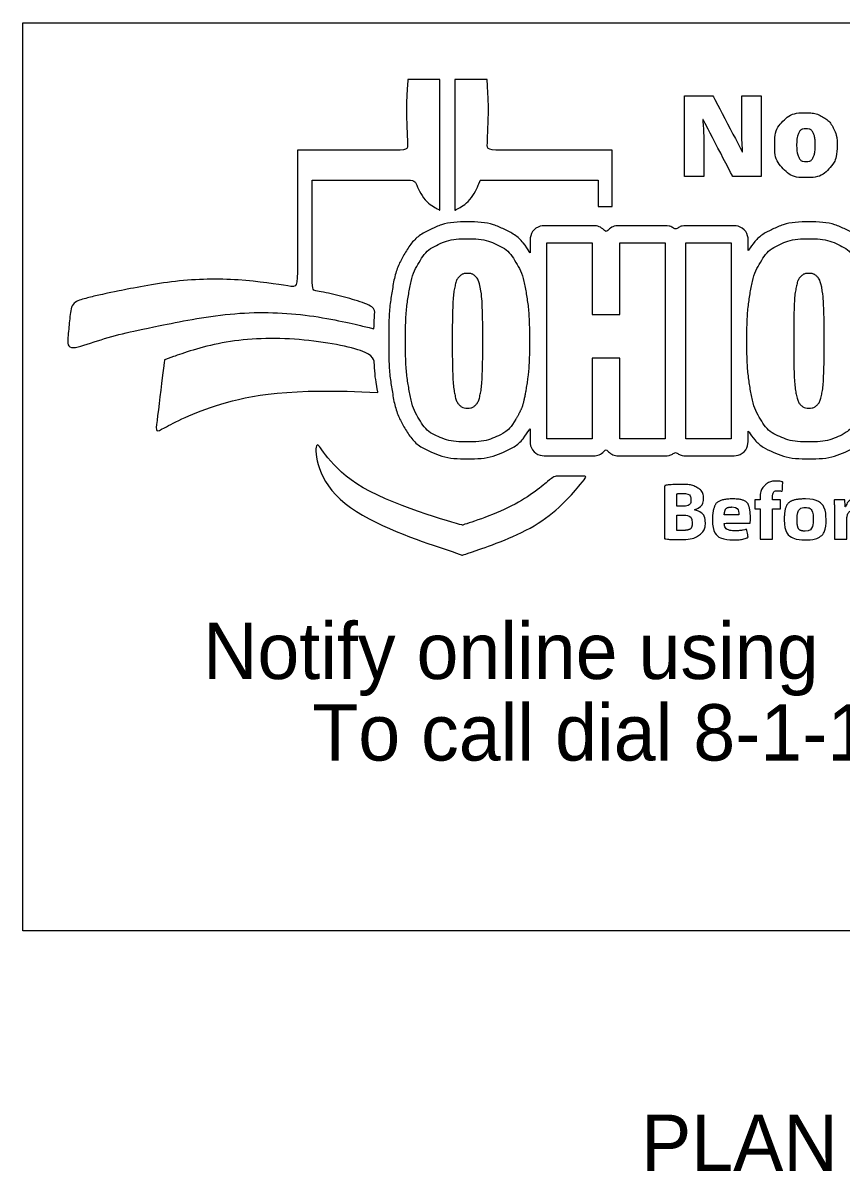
# Model space of a CAD drawing. Extents: x 0 to 70.2, y 0 to 31.4.
# Drawn here: x 40.226 to 42.259, y 11.816 to 14.667 of the extents above; entities that cross this region are included whole.
import ezdxf

# ---------------------------------------------------------------- set-up
doc = ezdxf.new("R2010")
doc.units = 0
for name, color, linetype in [('Default', 7, 'Continuous'), ('SH_Data', 7, 'Continuous'), ('SH_Text', 7, 'Continuous')]:
    doc.layers.add(name, color=color, linetype=linetype)

msp = doc.modelspace()

# ---------------------------------------------------------------- linework, layer by layer
at = {"layer": 'Default'}
for points, degree in [([(41.0979, 13.9079), (41.0979, 13.9079), (41.0978, 13.9079), (41.0978, 13.9079), (40.93, 13.9477), (40.7416, 13.9515), (40.5464, 13.9116), (40.4729, 13.8965), (40.402, 13.8758), (40.3341, 13.8504), (40.3379, 13.8906), (40.3419, 13.9332), (40.3457, 13.9734), (40.3777, 13.9822), (40.4099, 13.9906), (40.443, 13.9973), (40.6054, 14.0305), (40.7629, 14.0333), (40.9078, 14.0103), (40.9078, 14.0103), (40.9078, 14.3512), (40.9078, 14.3512), (40.9078, 14.3512), (41.1822, 14.3512), (41.1822, 14.3512), (41.1773, 14.46), (41.1822, 14.5269), (41.1822, 14.5269), (41.1822, 14.5269), (41.262, 14.5269), (41.262, 14.5269), (41.262, 14.5269), (41.262, 14.2022), (41.262, 14.2022), (41.262, 14.2022), (41.2221, 14.2228), (41.1987, 14.2769), (41.1987, 14.2769), (40.9446, 14.2769), (40.9446, 14.2769), (40.9446, 14.2769), (40.9446, 14.0038), (40.9446, 14.0038), (40.9988, 13.9935), (41.0512, 13.9795), (41.1012, 13.962), (41.0996, 13.9453), (41.0985, 13.9274), (41.0979, 13.9079)], 3), ([(41.3624, 14.277), (41.3624, 14.277), (41.3625, 14.277), (41.3625, 14.277), (41.339, 14.223), (41.2991, 14.2023), (41.2991, 14.2023), (41.2991, 14.2023), (41.2991, 14.5269), (41.2991, 14.5269), (41.2991, 14.5269), (41.3789, 14.5269), (41.3789, 14.5269), (41.3789, 14.5269), (41.3839, 14.46), (41.3789, 14.3512), (41.3789, 14.3512), (41.6898, 14.3512), (41.6898, 14.3512), (41.6898, 14.3512), (41.6898, 14.2115), (41.6898, 14.2115), (41.6898, 14.2115), (41.655, 14.2115), (41.655, 14.2115), (41.655, 14.2115), (41.655, 14.277), (41.655, 14.277), (41.655, 14.277), (41.3624, 14.277), (41.3624, 14.277)], 3), ([(42.0604, 14.286), (42.0604, 14.286), (42.0604, 14.4866), (42.0604, 14.4866), (42.0604, 14.4866), (42.0121, 14.4866), (42.0121, 14.4866), (42.0121, 14.4866), (42.0121, 14.3959), (42.0121, 14.3959), (42.0121, 14.3836), (42.0127, 14.3674), (42.014, 14.3472), (42.014, 14.3472), (42.0132, 14.3472), (42.0132, 14.3472), (42.0132, 14.3472), (41.9402, 14.4866), (41.9402, 14.4866), (41.9402, 14.4866), (41.8694, 14.4866), (41.8694, 14.4866), (41.8694, 14.4866), (41.8694, 14.286), (41.8694, 14.286), (41.8694, 14.286), (41.9174, 14.286), (41.9174, 14.286), (41.9174, 14.286), (41.9174, 14.3764), (41.9174, 14.3764), (41.9174, 14.3881), (41.9166, 14.4051), (41.9149, 14.4273), (41.9149, 14.4273), (41.9161, 14.4273), (41.9161, 14.4273), (41.9161, 14.4273), (41.9893, 14.286), (41.9893, 14.286), (41.9893, 14.286), (42.0604, 14.286), (42.0604, 14.286)], 3), ([(42.249, 14.3641), (42.249, 14.3803), (42.2458, 14.3944), (42.2394, 14.4065), (42.2331, 14.4186), (42.224, 14.4279), (42.2123, 14.4344), (42.2006, 14.4409), (42.1872, 14.4442), (42.1719, 14.4442), (42.1472, 14.4442), (42.128, 14.4371), (42.1143, 14.4231), (42.1007, 14.4091), (42.0938, 14.3894), (42.0938, 14.3641), (42.0938, 14.3393), (42.1008, 14.3196), (42.1148, 14.3051), (42.1287, 14.2905), (42.1475, 14.2833), (42.171, 14.2833), (42.1956, 14.2833), (42.2148, 14.2904), (42.2284, 14.3046), (42.2421, 14.3188), (42.249, 14.3387), (42.249, 14.3641)], 3), ([(42.1483, 14.3641), (42.1483, 14.3774), (42.15, 14.3874), (42.1536, 14.3941), (42.1572, 14.4009), (42.1631, 14.4042), (42.1714, 14.4042), (42.1797, 14.4042), (42.1857, 14.4009), (42.1891, 14.3941), (42.1926, 14.3873), (42.1944, 14.3773), (42.1944, 14.3641), (42.1944, 14.3507), (42.1927, 14.3406), (42.1893, 14.3336), (42.1858, 14.3266), (42.1799, 14.3231), (42.1716, 14.3231), (42.1632, 14.3231), (42.1572, 14.3266), (42.1536, 14.3336), (42.15, 14.3406), (42.1483, 14.3507), (42.1483, 14.3641)], 3), ([(42.6795, 14.1274), (42.6478, 14.1579), (42.6036, 14.1726), (42.5445, 14.1726), (42.4336, 14.1726), (42.3701, 14.1168), (42.364, 14.0153), (42.3577, 14.0465), (42.3483, 14.0725), (42.3353, 14.0942), (42.319, 14.1217), (42.2968, 14.1421), (42.2695, 14.155), (42.2442, 14.167), (42.2138, 14.1731), (42.179, 14.1731), (42.1442, 14.1731), (42.1139, 14.167), (42.0886, 14.155), (42.0638, 14.1433), (42.0436, 14.1251), (42.0278, 14.1014), (42.0278, 14.1014), (42.0278, 14.1215), (42.0278, 14.1215), (42.0278, 14.1447), (42.0089, 14.1635), (41.9857, 14.1635), (41.9857, 14.1635), (41.8735, 14.1635), (41.8735, 14.1635), (41.8635, 14.1635), (41.8547, 14.1595), (41.8475, 14.1538), (41.8402, 14.1595), (41.8314, 14.1635), (41.8215, 14.1635), (41.8215, 14.1635), (41.7092, 14.1635), (41.7092, 14.1635), (41.6949, 14.1635), (41.6824, 14.1565), (41.6748, 14.1456), (41.6672, 14.1565), (41.6546, 14.1635), (41.6404, 14.1635), (41.6404, 14.1635), (41.5281, 14.1635), (41.5281, 14.1635), (41.5049, 14.1635), (41.4861, 14.1448), (41.4861, 14.1215), (41.4861, 14.1215), (41.4861, 14.0953), (41.4861, 14.0953), (41.4698, 14.1222), (41.448, 14.1423), (41.421, 14.155), (41.3958, 14.167), (41.3653, 14.1731), (41.3305, 14.1731), (41.2957, 14.1731), (41.2653, 14.167), (41.2401, 14.155), (41.2127, 14.1421), (41.1907, 14.1217), (41.1742, 14.0942), (41.1595, 14.0695), (41.1489, 14.0381), (41.1429, 14.001), (41.1373, 13.9668), (41.1345, 13.9254), (41.1345, 13.878), (41.1345, 13.8306), (41.1373, 13.7891), (41.1429, 13.7549), (41.1489, 13.7178), (41.1595, 13.6864), (41.1742, 13.6617), (41.1908, 13.6339), (41.2134, 13.6135), (41.2411, 13.6014), (41.266, 13.5905), (41.2961, 13.5849), (41.3304, 13.5849), (41.3647, 13.5849), (41.3948, 13.5905), (41.4197, 13.6014), (41.4472, 13.6134), (41.4694, 13.6334), (41.486, 13.6606), (41.486, 13.6606), (41.486, 13.6344), (41.486, 13.6344), (41.486, 13.6113), (41.5048, 13.5924), (41.528, 13.5924), (41.528, 13.5924), (41.6403, 13.5924), (41.6403, 13.5924), (41.6546, 13.5924), (41.6671, 13.5995), (41.6747, 13.6103), (41.6823, 13.5995), (41.6948, 13.5924), (41.7091, 13.5924), (41.7091, 13.5924), (41.8214, 13.5924), (41.8214, 13.5924), (41.8313, 13.5924), (41.8401, 13.5964), (41.8474, 13.6022), (41.8546, 13.5964), (41.8634, 13.5924), (41.8734, 13.5924), (41.8734, 13.5924), (41.9856, 13.5924), (41.9856, 13.5924), (42.0088, 13.5924), (42.0277, 13.6112), (42.0277, 13.6344), (42.0277, 13.6344), (42.0277, 13.6546), (42.0277, 13.6546), (42.0437, 13.6305), (42.0644, 13.6125), (42.0896, 13.6014), (42.1145, 13.5905), (42.1446, 13.5849), (42.1789, 13.5849), (42.2132, 13.5849), (42.2433, 13.5905), (42.2683, 13.6014), (42.296, 13.6135), (42.3186, 13.6339), (42.3351, 13.6616), (42.3459, 13.6796), (42.3542, 13.7005), (42.3603, 13.7248), (42.3655, 13.6846), (42.3805, 13.652), (42.4056, 13.628), (42.4378, 13.5969), (42.4832, 13.5819), (42.5443, 13.5819), (42.6302, 13.5819), (42.6878, 13.6148), (42.7136, 13.6753), (42.7136, 13.6753), (42.7221, 13.6753), (42.7221, 13.6753), (42.7221, 13.6753), (42.7221, 13.6279), (42.7221, 13.6279), (42.7221, 13.6055), (42.7403, 13.5873), (42.7626, 13.5873), (42.7626, 13.5873), (42.8865, 13.5873), (42.8865, 13.5873), (42.9088, 13.5873), (42.927, 13.6055), (42.927, 13.6279), (42.927, 13.6279), (42.927, 13.9), (42.927, 13.9), (42.9284, 13.9), (42.9297, 13.8998), (42.931, 13.8998), (42.931, 13.8998), (42.931, 13.6279), (42.931, 13.6279), (42.931, 13.6055), (42.9492, 13.5873), (42.9716, 13.5873), (42.9716, 13.5873), (43.0954, 13.5873), (43.0954, 13.5873), (43.1103, 13.5873), (43.1232, 13.5955), (43.1302, 13.6074), (43.136, 13.5995), (43.1452, 13.5943), (43.1558, 13.5943), (43.1558, 13.5943), (43.2262, 13.5943), (43.2262, 13.5943), (43.2437, 13.5943), (43.258, 13.6085), (43.258, 13.6261), (43.258, 13.6261), (43.258, 13.6546), (43.258, 13.6546), (43.2594, 13.6513), (43.2604, 13.6477), (43.262, 13.6446), (43.2715, 13.6267), (43.2857, 13.6128), (43.3042, 13.6029), (43.3219, 13.5936), (43.3439, 13.589), (43.3715, 13.589), (43.399, 13.589), (43.4208, 13.5942), (43.4384, 13.6044), (43.4557, 13.6145), (43.4691, 13.6284), (43.4786, 13.6455), (43.4786, 13.6455), (43.4786, 13.6261), (43.4786, 13.6261), (43.4786, 13.6085), (43.4928, 13.5943), (43.5104, 13.5943), (43.5104, 13.5943), (43.5859, 13.5943), (43.5859, 13.5943), (43.6035, 13.5943), (43.6177, 13.6085), (43.6177, 13.6261), (43.6177, 13.6261), (43.6177, 13.7658), (43.6177, 13.7658), (43.6177, 13.7738), (43.6188, 13.7774), (43.6186, 13.7778), (43.6202, 13.7787), (43.6267, 13.7798), (43.6341, 13.7791), (43.6363, 13.7789), (43.6385, 13.7785), (43.641, 13.7781), (43.6426, 13.7778), (43.644, 13.7783), (43.6456, 13.7782), (43.6454, 13.772), (43.6449, 13.7665), (43.6449, 13.7597), (43.6449, 13.7303), (43.6472, 13.7067), (43.6519, 13.6875), (43.6566, 13.6683), (43.6628, 13.653), (43.6707, 13.6409), (43.6677, 13.6393), (43.6649, 13.6373), (43.6625, 13.6348), (43.6565, 13.6288), (43.6532, 13.6205), (43.6534, 13.612), (43.6537, 13.5928), (43.6573, 13.5762), (43.6641, 13.5627), (43.6711, 13.5484), (43.6811, 13.5369), (43.6937, 13.5283), (43.7052, 13.5206), (43.7185, 13.5152), (43.7332, 13.5124), (43.7458, 13.5099), (43.7592, 13.5087), (43.7733, 13.5087), (43.7893, 13.5087), (43.8046, 13.5105), (43.8188, 13.5142), (43.8347, 13.5184), (43.8488, 13.5255), (43.8607, 13.5353), (43.8733, 13.5454), (43.8832, 13.559), (43.8901, 13.5755), (43.8966, 13.5911), (43.9, 13.6095), (43.9, 13.6304), (43.9, 13.6304), (43.9, 13.8824), (43.9, 13.8824), (43.9, 13.9), (43.8857, 13.9142), (43.8681, 13.9142), (43.8681, 13.9142), (43.8681, 13.9141), (43.8681, 13.9141)], 3), ([(41.4505, 13.6832), (41.4384, 13.663), (41.4226, 13.6485), (41.4028, 13.6399), (41.3831, 13.6313), (41.3589, 13.6269), (41.3303, 13.6269), (41.3017, 13.6269), (41.2775, 13.6312), (41.2579, 13.6399), (41.2381, 13.6485), (41.2223, 13.663), (41.2102, 13.6832), (41.1981, 13.7034), (41.1895, 13.7296), (41.1842, 13.7617), (41.1789, 13.7937), (41.1764, 13.8325), (41.1764, 13.878), (41.1764, 13.9234), (41.179, 13.9622), (41.1842, 13.9943), (41.1895, 14.0263), (41.1981, 14.0525), (41.2102, 14.0727), (41.2223, 14.093), (41.2381, 14.1077), (41.2579, 14.1171), (41.2776, 14.1265), (41.3018, 14.1311), (41.3303, 14.1311), (41.3588, 14.1311), (41.3831, 14.1264), (41.4028, 14.1171), (41.4226, 14.1078), (41.4384, 14.093), (41.4505, 14.0727), (41.4626, 14.0525), (41.4712, 14.0263), (41.4765, 13.9943), (41.4817, 13.9622), (41.4843, 13.9234), (41.4843, 13.878), (41.4843, 13.8325), (41.4817, 13.7937), (41.4765, 13.7617)], 3), ([(41.709, 13.6344), (41.709, 13.6344), (41.709, 13.8351), (41.709, 13.8351), (41.709, 13.8351), (41.6402, 13.8351), (41.6402, 13.8351), (41.6402, 13.8351), (41.6402, 13.6344), (41.6402, 13.6344), (41.6402, 13.6344), (41.5279, 13.6344), (41.5279, 13.6344), (41.5279, 13.6344), (41.5279, 14.1216), (41.5279, 14.1216), (41.5279, 14.1216), (41.6402, 14.1216), (41.6402, 14.1216), (41.6402, 14.1216), (41.6402, 13.9429), (41.6402, 13.9429), (41.6402, 13.9429), (41.709, 13.9429), (41.709, 13.9429), (41.709, 13.9429), (41.709, 14.1216), (41.709, 14.1216), (41.709, 14.1216), (41.8213, 14.1216), (41.8213, 14.1216), (41.8213, 14.1216), (41.8213, 13.6344), (41.8213, 13.6344)], 3), ([(41.8732, 13.6344), (41.8732, 13.6344), (41.8732, 14.1216), (41.8732, 14.1216), (41.8732, 14.1216), (41.9854, 14.1216), (41.9854, 14.1216), (41.9854, 14.1216), (41.9854, 13.6344), (41.9854, 13.6344)], 3), ([(42.2988, 13.6832), (42.2867, 13.663), (42.2709, 13.6485), (42.2512, 13.6399), (42.2314, 13.6313), (42.2073, 13.6269), (42.1786, 13.6269), (42.15, 13.6269), (42.1259, 13.6312), (42.1062, 13.6399), (42.0865, 13.6485), (42.0707, 13.663), (42.0585, 13.6832), (42.0464, 13.7034), (42.0378, 13.7296), (42.0325, 13.7617), (42.0273, 13.7937), (42.0247, 13.8325), (42.0247, 13.878), (42.0247, 13.9234), (42.0274, 13.9622), (42.0325, 13.9943), (42.0378, 14.0263), (42.0464, 14.0525), (42.0585, 14.0727), (42.0707, 14.093), (42.0865, 14.1077), (42.1062, 14.1171), (42.126, 14.1265), (42.1501, 14.1311), (42.1786, 14.1311), (42.2072, 14.1311), (42.2314, 14.1264), (42.2512, 14.1171), (42.2709, 14.1078), (42.2867, 14.093), (42.2988, 14.0727), (42.311, 14.0525), (42.3196, 14.0263), (42.3248, 13.9943), (42.33, 13.9622), (42.3327, 13.9234), (42.3327, 13.878), (42.3327, 13.8325), (42.33, 13.7937), (42.3248, 13.7617)], 3), ([(41.3621, 14.011), (41.3646, 13.9983), (41.3664, 13.9811), (41.3671, 13.9595), (41.3679, 13.9379), (41.3683, 13.9107), (41.3683, 13.878), (41.3683, 13.8452), (41.3679, 13.8181), (41.3671, 13.7965), (41.3664, 13.7749), (41.3647, 13.7577), (41.3621, 13.745), (41.3594, 13.7323), (41.3556, 13.7234), (41.3506, 13.7184), (41.3456, 13.7134), (41.3389, 13.7109), (41.3304, 13.7109), (41.3219, 13.7109), (41.3153, 13.7134), (41.3102, 13.7184), (41.3052, 13.7234), (41.3014, 13.7323), (41.2987, 13.745), (41.2962, 13.7577), (41.2944, 13.7749), (41.2937, 13.7965), (41.2929, 13.8181), (41.2925, 13.8452), (41.2925, 13.878), (41.2925, 13.9107), (41.2929, 13.9379), (41.2937, 13.9595), (41.2944, 13.9811), (41.2961, 13.9983), (41.2987, 14.011), (41.3013, 14.0237), (41.3051, 14.0326), (41.3102, 14.0376), (41.3153, 14.0425), (41.3219, 14.0451), (41.3304, 14.0451), (41.3389, 14.0451), (41.3455, 14.0425), (41.3506, 14.0376), (41.3556, 14.0326), (41.3594, 14.0237), (41.3621, 14.011)], 3), ([(42.2105, 14.011), (42.213, 13.9983), (42.2148, 13.9811), (42.2156, 13.9595), (42.2164, 13.9379), (42.2168, 13.9107), (42.2168, 13.878), (42.2168, 13.8452), (42.2164, 13.8181), (42.2156, 13.7965), (42.2148, 13.7749), (42.2131, 13.7577), (42.2105, 13.745), (42.2079, 13.7323), (42.2041, 13.7234), (42.1991, 13.7184), (42.1941, 13.7134), (42.1873, 13.7109), (42.1788, 13.7109), (42.1703, 13.7109), (42.1637, 13.7134), (42.1586, 13.7184), (42.1536, 13.7234), (42.1498, 13.7323), (42.1472, 13.745), (42.1446, 13.7577), (42.1429, 13.7749), (42.1421, 13.7965), (42.1413, 13.8181), (42.1409, 13.8452), (42.1409, 13.878), (42.1409, 13.9107), (42.1413, 13.9379), (42.1421, 13.9595), (42.1429, 13.9811), (42.1445, 13.9983), (42.1472, 14.011), (42.1497, 14.0237), (42.1535, 14.0326), (42.1586, 14.0376), (42.1637, 14.0425), (42.1703, 14.0451), (42.1788, 14.0451), (42.1873, 14.0451), (42.194, 14.0425), (42.1991, 14.0376), (42.2041, 14.0326), (42.2079, 14.0237), (42.2105, 14.011)], 3), ([(41.1078, 13.7492), (40.8886, 13.7617), (40.6907, 13.723), (40.5552, 13.6498), (40.5552, 13.6498), (40.5771, 13.8283), (40.5771, 13.8283), (40.5771, 13.8283), (40.5771, 13.8304), (40.5771, 13.8304), (40.7124, 13.879), (40.8978, 13.8895), (41.0978, 13.8533), (41.0987, 13.8184), (41.101, 13.7877), (41.1053, 13.7616), (41.106, 13.7573), (41.1069, 13.7533), (41.1078, 13.7492)], 3), ([(41.4765, 13.7617), (41.4712, 13.7296), (41.4626, 13.7034), (41.4505, 13.6832)], 2), ([(41.8213, 13.6344), (41.8213, 13.6344), (41.709, 13.6344), (41.709, 13.6344)], 2), ([(41.9854, 13.6344), (41.9854, 13.6344), (41.8732, 13.6344), (41.8732, 13.6344)], 2), ([(41.3178, 13.4201), (41.3178, 13.4201), (41.447, 13.4598), (41.5455, 13.5417), (41.5455, 13.5417), (41.6282, 13.5417), (41.6282, 13.5417), (41.5223, 13.4152), (41.3176, 13.3455), (41.3176, 13.3455), (41.3176, 13.3455), (40.9555, 13.4687), (40.9454, 13.6854), (41.0017, 13.5031), (41.3178, 13.4201), (41.3178, 13.4201)], 3), ([(41.8942, 13.4583), (41.9096, 13.4639), (41.9167, 13.4751), (41.9167, 13.4871), (41.9167, 13.4991), (41.9098, 13.5084), (41.9003, 13.5134), (41.8904, 13.5191), (41.8787, 13.521), (41.8599, 13.521), (41.8444, 13.521), (41.8279, 13.5198), (41.8198, 13.5182), (41.8198, 13.5182), (41.8198, 13.3862), (41.8198, 13.3862), (41.8267, 13.3852), (41.8381, 13.3843), (41.8533, 13.3843), (41.8806, 13.3843), (41.8973, 13.3887), (41.9073, 13.3964), (41.9158, 13.4031), (41.9214, 13.4127), (41.9214, 13.4249), (41.9214, 13.4423), (41.9098, 13.4539), (41.8942, 13.4581)], 3), ([(42.0699, 13.5195), (42.0699, 13.5195), (42.0699, 13.5195), (42.0699, 13.5195), (42.0776, 13.5267), (42.0883, 13.5293), (42.0973, 13.5293), (42.1043, 13.5293), (42.1096, 13.5285), (42.1139, 13.5273), (42.1139, 13.5273), (42.1126, 13.504), (42.1126, 13.504), (42.1099, 13.5048), (42.1067, 13.5054), (42.1026, 13.5054), (42.0925, 13.5054), (42.0882, 13.4976), (42.0882, 13.4881), (42.0882, 13.4881), (42.0882, 13.4831), (42.0882, 13.4831), (42.0882, 13.4831), (42.1081, 13.4831), (42.1081, 13.4831), (42.1081, 13.4831), (42.1081, 13.4608), (42.1081, 13.4608), (42.1081, 13.4608), (42.0883, 13.4608), (42.0883, 13.4608), (42.0883, 13.4608), (42.0883, 13.3856), (42.0883, 13.3856), (42.0883, 13.3856), (42.0573, 13.3856), (42.0573, 13.3856), (42.0573, 13.3856), (42.0573, 13.4608), (42.0573, 13.4608), (42.0573, 13.4608), (42.0443, 13.4608), (42.0443, 13.4608), (42.0443, 13.4608), (42.0443, 13.4831), (42.0443, 13.4831), (42.0443, 13.4831), (42.0573, 13.4831), (42.0573, 13.4831), (42.0573, 13.4831), (42.0573, 13.4869), (42.0573, 13.4869), (42.0573, 13.4986), (42.0609, 13.5115), (42.0699, 13.5195)], 3), ([(41.8637, 13.4988), (41.8777, 13.4988), (41.8857, 13.4934), (41.8857, 13.4833), (41.8857, 13.4731), (41.8769, 13.4668), (41.8607, 13.4668), (41.8607, 13.4668), (41.8505, 13.4668), (41.8505, 13.4668), (41.8505, 13.4668), (41.8505, 13.498), (41.8505, 13.498), (41.8505, 13.498), (41.8505, 13.498), (41.8505, 13.498)], 3), ([(41.8505, 13.498), (41.8531, 13.4984), (41.8569, 13.4988), (41.8637, 13.4988)], 2), ([(41.9891, 13.4852), (41.9545, 13.4852), (41.9389, 13.4579), (41.9389, 13.4332)], 2), ([(41.9874, 13.4651), (42.0017, 13.4651), (42.0049, 13.4528), (42.0049, 13.4453), (42.0049, 13.4453), (41.9682, 13.4453), (41.9682, 13.4453)], 3), ([(41.9682, 13.4453), (41.969, 13.4536), (41.9743, 13.4651), (41.9874, 13.4651)], 2), ([(41.9891, 13.4852), (41.9891, 13.4852), (41.9891, 13.4852), (41.9892, 13.4852)], 2), ([(41.9892, 13.4852), (41.9892, 13.4852), (41.9891, 13.4852), (41.9891, 13.4852)], 2), ([(41.9891, 13.4852), (41.9891, 13.4852), (41.9891, 13.4852), (41.9891, 13.4852)], 2), ([(42.0334, 13.4366), (42.0334, 13.4607), (42.0212, 13.4852), (41.9891, 13.4852)], 2), ([(42.1174, 13.4336), (42.1174, 13.4022), (42.1398, 13.3834), (42.1688, 13.3834), (42.1955, 13.3834), (42.2213, 13.3997), (42.2213, 13.4354), (42.2213, 13.4647), (42.2009, 13.4852), (42.1704, 13.4852)], 3), ([(42.1704, 13.4852), (42.1385, 13.4852), (42.1174, 13.4651), (42.1174, 13.4336)], 2), ([(42.1493, 13.4344), (42.1493, 13.4488), (42.1548, 13.4637), (42.1697, 13.4637), (42.1836, 13.4637), (42.1894, 13.449), (42.1894, 13.4344), (42.1894, 13.4168), (42.1817, 13.4051), (42.1697, 13.4051)], 3), ([(42.2698, 13.4651), (42.2698, 13.4651), (42.2698, 13.4652), (42.2698, 13.4652), (42.2749, 13.4794), (42.2871, 13.4853), (42.2967, 13.4853), (42.2995, 13.4853), (42.301, 13.4853), (42.3032, 13.4849), (42.3032, 13.4849), (42.3032, 13.4564), (42.3032, 13.4564), (42.301, 13.4568), (42.2985, 13.4572), (42.2949, 13.4572), (42.2835, 13.4572), (42.2758, 13.4512), (42.2737, 13.4418), (42.2733, 13.4399), (42.2731, 13.4374), (42.2731, 13.4351), (42.2731, 13.4351), (42.2731, 13.3856), (42.2731, 13.3856), (42.2731, 13.3856), (42.2422, 13.3856), (42.2422, 13.3856), (42.2422, 13.3856), (42.2422, 13.451), (42.2422, 13.451), (42.2422, 13.4653), (42.2418, 13.4747), (42.2414, 13.4831), (42.2414, 13.4831), (42.2681, 13.4831), (42.2681, 13.4831), (42.2681, 13.4831), (42.269, 13.4651), (42.269, 13.4651), (42.269, 13.4651), (42.2698, 13.4651), (42.2698, 13.4651)], 3), ([(41.8505, 13.4071), (41.8505, 13.4071), (41.8505, 13.4451), (41.8505, 13.4451), (41.8505, 13.4451), (41.861, 13.4451), (41.861, 13.4451), (41.8765, 13.4451), (41.8889, 13.4397), (41.8889, 13.4261)], 3), ([(41.8942, 13.4581), (41.8942, 13.4582), (41.8942, 13.4583), (41.8942, 13.4583)], 2), ([(41.9389, 13.4332), (41.9389, 13.4027), (41.9583, 13.3836), (41.992, 13.3836), (42.0054, 13.3836), (42.0178, 13.3855), (42.028, 13.3895), (42.028, 13.3895), (42.0239, 13.4101), (42.0239, 13.4101), (42.0155, 13.4074), (42.0069, 13.4061), (41.9964, 13.4061), (41.9819, 13.4061), (41.9693, 13.412), (41.9683, 13.4246), (41.9683, 13.4246), (42.0325, 13.4246), (42.0325, 13.4246), (42.0328, 13.4268), (42.0334, 13.4314), (42.0334, 13.4366)], 3), ([(42.1697, 13.4051), (42.1565, 13.4051), (42.1493, 13.4176), (42.1493, 13.4344)], 2), ([(41.8625, 13.4067), (41.8572, 13.4067), (41.8536, 13.4067), (41.8505, 13.4071)], 2), ([(41.8889, 13.4261), (41.8889, 13.4125), (41.8765, 13.4068), (41.8625, 13.4067)], 2)]:
    msp.add_open_spline(points, degree=degree, dxfattribs=at)
at = {"layer": 'SH_Data'}
msp.add_lwpolyline([(40.2257, 14.6673), (45.0774, 14.6673), (45.0774, 12.4128), (40.2257, 12.4128)], close=True, dxfattribs=at)

# ---------------------------------------------------------------- texts
for s, p in [('Notify online using ', (40.6731, 13.0378)), ('To call dial 8-1-1 or 800-362-2764', (40.9446, 12.8353))]:
    msp.add_text(s, height=0.14, dxfattribs=at).set_placement(p)
at = {"layer": 'SH_Text'}
msp.add_text('PLAN PREPARED BY:', height=0.14, dxfattribs=at).set_placement((41.7615, 11.8158))

doc.saveas('drawing.dxf')
